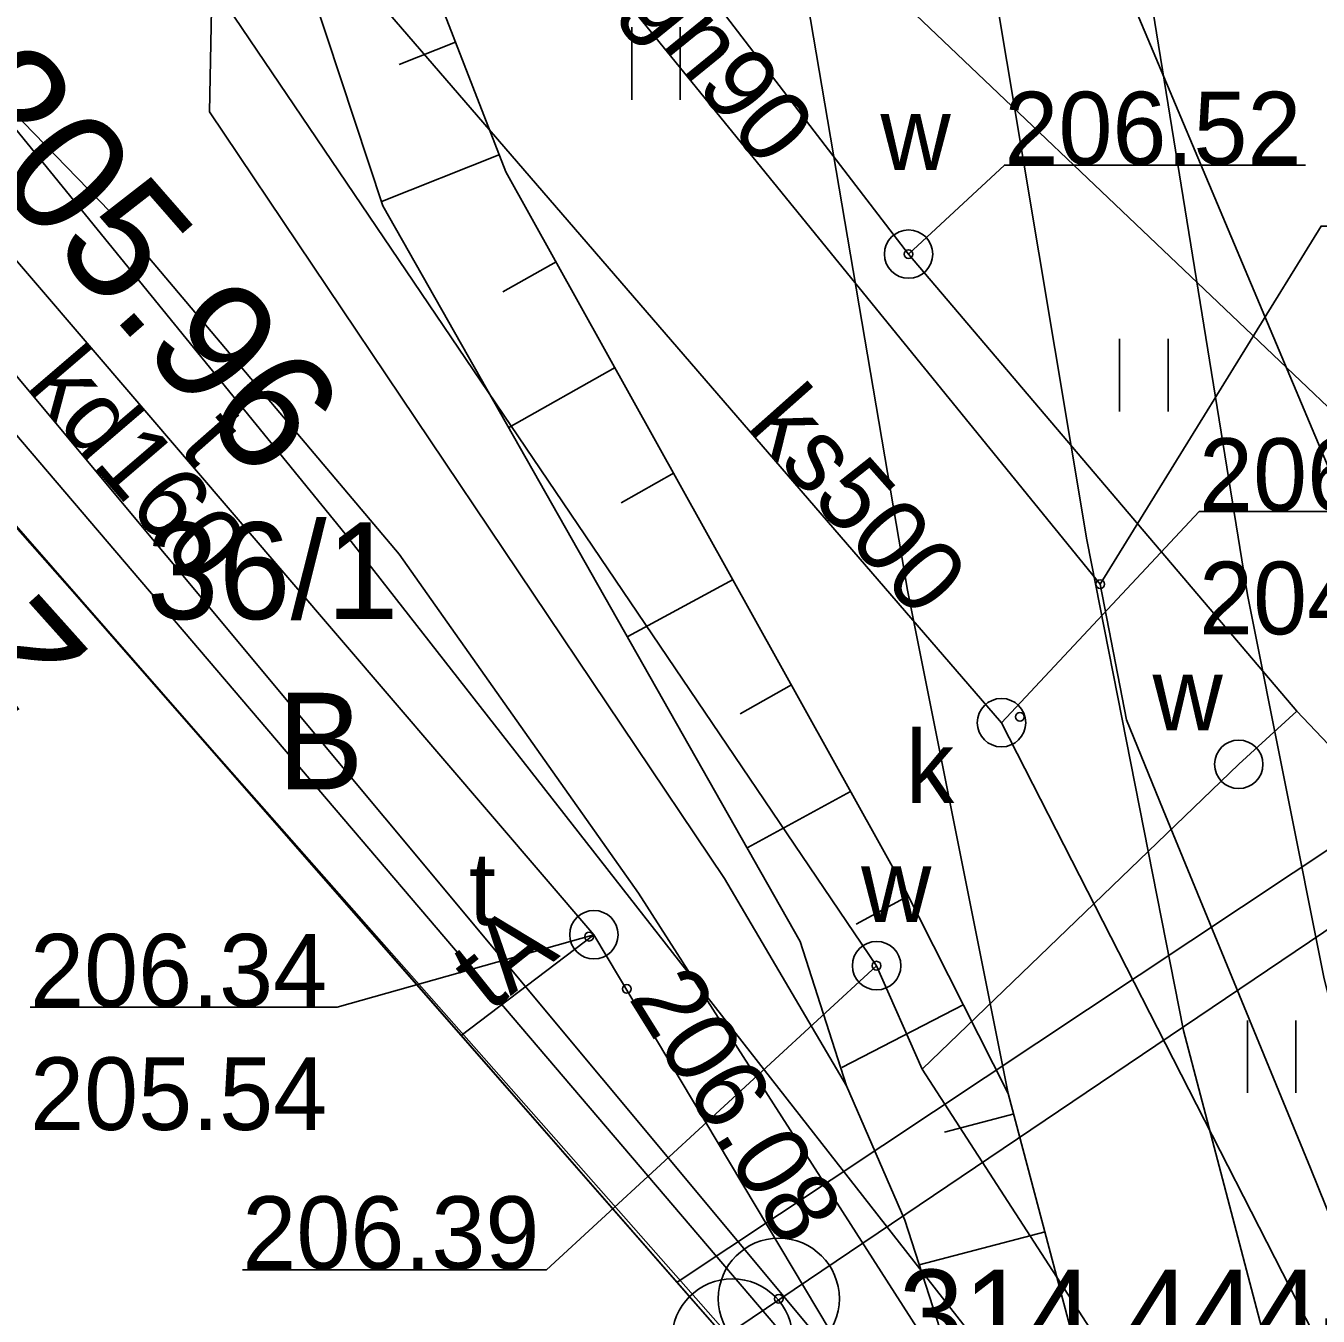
# Model space of a CAD drawing. Extents: x 6512400 to 6513200, y 6022500 to 6022750.
# Drawn here: x 6512830.73 to 6512844.08, y 6022634.38 to 6022647.71 of the extents above; entities that cross this region are included whole.
import ezdxf

# ---------------------------------------------------------------- set-up
doc = ezdxf.new("R2010")
doc.units = 0
for name, color, linetype in [('121-Punkt osnowy szczegółowej', 7, 'Continuous'), ('121-Punkt osnowy szczegółowej-Atr103', 7, 'Continuous'), ('210-oznaczenie konturu użytku gruntowego', 7, 'Continuous'), ('211-numer działki ewidencyjnej', 7, 'Continuous'), ('216-obręb ewidencyjny', 7, 'Continuous'), ('218-kontur użytku gruntowego', 7, 'Continuous'), ('219-działka ewidencyjna', 7, 'Continuous'), ('238-Punkt adresowy budynku', 7, 'Continuous'), ('312-budynek ewidencyjny', 7, 'Continuous'), ('820-Skarpa nieumocniona', 7, 'Continuous'), ('823-Szczyt skarpy nieumocninej', 7, 'Continuous'), ('824-Podnóże skarpy nieumocninej', 7, 'Continuous'), ('940-Trawnik symb. poj.', 7, 'Continuous'), ('chodnik (powierzchnia)', 7, 'Continuous'), ('krawężnik (linia)', 7, 'Continuous'), ('przewód ciepłowniczy (linia)', 7, 'Continuous'), ('przewód elektroenergetyczny (linia)', 7, 'Continuous'), ('przewód gazowy (linia)', 7, 'Continuous'), ('przewód gazowy (linia)-Atr1', 7, 'Continuous'), ('przewód kanalizacyjny (linia)', 7, 'Continuous'), ('przewód kanalizacyjny (linia)-Atr1', 7, 'Continuous'), ('przewód telekomunikacyjny (linia)', 7, 'Continuous'), ('przewód telekomunikacyjny (linia)-Atr1', 7, 'Continuous'), ('przewód wodociągowy (linia)', 7, 'Continuous'), ('punkt o określonej wysokości (sieć gazowa)', 7, 'Continuous'), ('punkt o określonej wysokości (sieć gazowa)-Atr2', 7, 'Continuous'), ('punkt o określonej wysokości (sieć kanalizacyjna)', 7, 'Continuous'), ('punkt o określonej wysokości (sieć kanalizacyjna)-Atr2', 7, 'Continuous'), ('punkt o określonej wysokości (sieć kanalizacyjna)-Atr3', 7, 'Continuous'), ('punkt o określonej wysokości (sieć telekomunikacyjna)', 7, 'Continuous'), ('punkt o określonej wysokości (sieć telekomunikacyjna)-Atr2', 7, 'Continuous'), ('punkt o określonej wysokości (sieć telekomunikacyjna)-Atr3', 7, 'Continuous'), ('punkt o określonej wysokości (sieć wodociągowa)', 7, 'Continuous'), ('punkt o określonej wysokości (sieć wodociągowa)-Atr2', 7, 'Continuous'), ('rura ochronna - przewód gazowy (linia)', 7, 'Continuous'), ('właz okrągły - siec kanalizacyjna (punkt)', 7, 'Continuous'), ('właz okrągły - siec kanalizacyjna (punkt)-Atr17', 7, 'Continuous'), ('właz okrągły - siec telekomunikacyjna (punkt)', 7, 'Continuous'), ('właz okrągły - siec telekomunikacyjna (punkt)-Atr17', 7, 'Continuous'), ('właz okrągły - siec wodociągowa (punkt)', 7, 'Continuous'), ('właz okrągły - siec wodociągowa (punkt)-Atr17', 7, 'Continuous')]:
    doc.layers.add(name, color=color, linetype=linetype)

# ---------------------------------------------------------------- blocks, each defined once
blk = doc.blocks.new('PW01')
blk.add_circle((0, 0), 0.045)
blk = doc.blocks.new('US22')
blk.add_circle((0, 0), 0.25)
blk = doc.blocks.new('940P')
for p, q in [((-0.25, -0.375), (-0.25, 0.375)), ((0.25, -0.375), (0.25, 0.375))]:
    blk.add_line(p, q)
blk = doc.blocks.new('121')
for radius in [0.625, 0.045]:
    blk.add_circle((0, 0), radius)

msp = doc.modelspace()

# ---------------------------------------------------------------- linework, layer by layer
at = {"layer": '216-obręb ewidencyjny'}
for points in [[(6512836.687, 6022675.173), (6512833.61, 6022675.02), (6512828.67, 6022670.98), (6512801.96, 6022670.34), (6512810.18, 6022663.28), (6512825.37, 6022649.66), (6512838.47, 6022634.29), (6512852.25, 6022608.25), (6512853.17, 6022604.51), (6512855.78, 6022583.95), (6512858.85, 6022571.74), (6512828.23, 6022562.62), (6512818.47, 6022559.72), (6512824.714, 6022553.406)], [(6512780.7, 6022581.02), (6512806.2, 6022572.11), (6512806.62, 6022563.51), (6512811.41, 6022558.95), (6512818.47, 6022559.72), (6512828.23, 6022562.62), (6512858.85, 6022571.74), (6512855.78, 6022583.95), (6512853.17, 6022604.51), (6512852.25, 6022608.25), (6512838.47, 6022634.29), (6512825.37, 6022649.66), (6512810.18, 6022663.28), (6512801.96, 6022670.34), (6512796.96, 6022674.74), (6512790.49, 6022674.74), (6512785.56, 6022674.74), (6512768.24, 6022674.27)]]:
    msp.add_lwpolyline(points, dxfattribs=at)
at = {"layer": '218-kontur użytku gruntowego'}
for points in [[(6512835.81, 6022651.74), (6512852.34, 6022636.01)], [(6512852.34, 6022636.01), (6512835.81, 6022651.74)], [(6512838.47, 6022634.29), (6512825.37, 6022649.66)], [(6512825.37, 6022649.66), (6512838.47, 6022634.29)], [(6512838.09, 6022634.07), (6512824.77, 6022649.17)], [(6512824.77, 6022649.17), (6512838.09, 6022634.07)]]:
    msp.add_lwpolyline(points, dxfattribs=at)
at = {"layer": '219-działka ewidencyjna'}
for points in [[(6512852.34, 6022636.01), (6512835.81, 6022651.74)], [(6512838.47, 6022634.29), (6512825.37, 6022649.66)], [(6512824.77, 6022649.17), (6512838.09, 6022634.07)]]:
    msp.add_lwpolyline(points, dxfattribs=at)
at = {"layer": '312-budynek ewidencyjny'}
msp.add_lwpolyline([(6512824.72, 6022649.31), (6512838.13, 6022633.96)], dxfattribs=at)
at = {"layer": '820-Skarpa nieumocniona'}
for p, q in [((6512835.17, 6022647.54), (6512834.59, 6022647.31)), ((6512835.63, 6022646.38), (6512834.4, 6022645.89)), ((6512836.21, 6022645.27), (6512835.66, 6022644.96)), ((6512836.82, 6022644.18), (6512835.72, 6022643.56)), ((6512837.43, 6022643.09), (6512836.88, 6022642.78)), ((6512838.04, 6022641.99), (6512836.95, 6022641.4)), ((6512838.64, 6022640.9), (6512838.11, 6022640.6)), ((6512839.25, 6022639.8), (6512838.19, 6022639.22)), ((6512839.85, 6022638.72), (6512839.31, 6022638.43)), ((6512840.42, 6022637.6), (6512839.16, 6022636.95)), ((6512840.94, 6022636.47), (6512840.22, 6022636.28)), ((6512841.26, 6022635.25), (6512839.96, 6022634.91))]:
    msp.add_line(p, q, dxfattribs=at)
at = {"layer": '823-Szczyt skarpy nieumocninej'}
msp.add_lwpolyline([(6512833.8, 6022651.69), (6512834.92, 6022648.19), (6512835.69, 6022646.2), (6512839.8, 6022638.81), (6512840.88, 6022636.68), (6512842.42, 6022630.86), (6512843.78, 6022626.35)], dxfattribs=at)
at = {"layer": '824-Podnóże skarpy nieumocninej'}
msp.add_lwpolyline([(6512843.78, 6022626.35), (6512842.81, 6022626.09), (6512839.81, 6022635.37), (6512839.21, 6022636.76), (6512838.73, 6022638.25), (6512834.42, 6022645.85), (6512833.69, 6022648.06), (6512833.8, 6022651.69)], dxfattribs=at)
at = {"layer": 'chodnik (powierzchnia)'}
msp.add_lwpolyline([(6512845.61, 6022610.5), (6512844.69, 6022613.44), (6512844.06, 6022613.28), (6512843.41, 6022615.01), (6512844.01, 6022615.23), (6512838.87, 6022629.83), (6512839.52, 6022630.32), (6512838.94, 6022631.84), (6512838.15, 6022631.88), (6512837.86, 6022632.79), (6512838.13, 6022633.96), (6512826.89, 6022646.81), (6512825.11, 6022648.85), (6512824.32, 6022649.76), (6512820.29, 6022654.03), (6512817.62, 6022656.88), (6512816.1, 6022658.5), (6512810.3, 6022663.44), (6512802.06, 6022670.47), (6512797.05, 6022674.74)], dxfattribs=at)
for points in [[(6512832.77, 6022654.07), (6512832.63, 6022646.82), (6512837.95, 6022638.9), (6512839.21, 6022636.76), (6512839.81, 6022635.37), (6512842.81, 6022626.09), (6512843.78, 6022626.35), (6512842.42, 6022630.86), (6512840.88, 6022636.68), (6512839.84, 6022641.88), (6512838.78, 6022648.12), (6512838.09, 6022653.46), (6512836.3, 6022653.4), (6512834.86, 6022653.53), (6512833.61, 6022653.83)], [(6512840.07, 6022653.59), (6512840.7, 6022648.33), (6512841.69, 6022642.4), (6512842.69, 6022637.33), (6512844.27, 6022631.32), (6512848.17, 6022618.59), (6512848.25, 6022618.32), (6512848.4, 6022617.84), (6512848.64, 6022617), (6512849.8, 6022613.04), (6512850.26, 6022613.71), (6512850.75, 6022614.71), (6512849.55, 6022618.93), (6512847.18, 6022626.74), (6512845.1, 6022633.98), (6512844.14, 6022637.88), (6512843.35, 6022641.83), (6512842.14, 6022649.32), (6512841.8, 6022651.66)]]:
    msp.add_lwpolyline(points, close=True, dxfattribs=at)
at = {"layer": 'krawężnik (linia)'}
msp.add_lwpolyline([(6512841.8, 6022651.66), (6512842.14, 6022649.32), (6512843.35, 6022641.83), (6512844.14, 6022637.88), (6512845.1, 6022633.98), (6512847.18, 6022626.74), (6512849.55, 6022618.93), (6512850.75, 6022614.71)], dxfattribs=at)
at = {"layer": 'przewód ciepłowniczy (linia)'}
for points in [[(6512837.46, 6022634.73), (6512851.24, 6022643.89)], [(6512852.19, 6022643.78), (6512837.95, 6022634.17)]]:
    msp.add_lwpolyline(points, dxfattribs=at)
at = {"layer": 'przewód elektroenergetyczny (linia)'}
for points in [[(6512763.38, 6022676.06), (6512798.79, 6022676.04), (6512803.06, 6022673.02), (6512807.84, 6022668.96), (6512815.24, 6022662.53), (6512819.98, 6022657.77), (6512831.6, 6022645.79), (6512834.59, 6022642.25), (6512837.06, 6022638.75), (6512840.02, 6022634.13), (6512842.26, 6022630.04), (6512846.03, 6022621.35), (6512846.58, 6022618.9), (6512847.6, 6022616.23), (6512852.12, 6022605.09), (6512853.39, 6022601.13), (6512855.57, 6022592.48), (6512858.1, 6022582.86), (6512868.09, 6022584.49), (6512870.03, 6022584.23), (6512871.36, 6022584.34), (6512875.65, 6022585.56), (6512879.74, 6022586.61), (6512881.754, 6022587.357)], [(6512802.27, 6022673.66), (6512807.42, 6022670.09), (6512811.38, 6022666.87), (6512814.66, 6022663.43), (6512826.4, 6022651.65), (6512827.82, 6022650.09), (6512834.03, 6022642.46), (6512842.84, 6022631.19), (6512844.67, 6022626.95), (6512847.57, 6022619.87), (6512849.81, 6022612.67), (6512853.56, 6022600.08), (6512856.46, 6022588.83), (6512861.26, 6022569.82), (6512861.768, 6022567.654)]]:
    msp.add_lwpolyline(points, dxfattribs=at)
at = {"layer": 'przewód gazowy (linia)'}
msp.add_lwpolyline([(6512847.18, 6022613.76), (6512846.63, 6022615.41), (6512849.08, 6022617.22), (6512845.94, 6022626.61), (6512846.16, 6022628.38), (6512844.18, 6022631.79), (6512844.23, 6022632.26), (6512844.43, 6022634.25), (6512844.47, 6022634.75), (6512844, 6022635.91), (6512842.48, 6022639.61), (6512842.1, 6022640.54), (6512841.83, 6022641.94), (6512833.52, 6022652.16), (6512828.68, 6022655.12), (6512826.33, 6022655.65), (6512824.93, 6022656.06), (6512819.76, 6022660.64)], dxfattribs=at)
at = {"layer": 'przewód kanalizacyjny (linia)'}
for points in [[(6512809.75, 6022675.66), (6512823.01, 6022660.61), (6512831.4, 6022651.41), (6512840.81, 6022640.51)], [(6512853.94, 6022620), (6512836.1, 6022662.34)], [(6512825.42, 6022650.35), (6512838.94, 6022634.13)], [(6512853.7, 6022614.72), (6512848.55, 6022625.36), (6512840.81, 6022640.51)]]:
    msp.add_lwpolyline(points, dxfattribs=at)
at = {"layer": 'przewód telekomunikacyjny (linia)'}
for points in [[(6512829.25, 6022646.9), (6512836.6, 6022638.32)], [(6512836.6, 6022638.32), (6512835.23, 6022637.28)], [(6512836.6, 6022638.32), (6512844.42, 6022625.21), (6512848.91, 6022613.6), (6512851.86, 6022605.02), (6512853.91, 6022597.19), (6512860.14, 6022571.94), (6512860.33, 6022571.18)]]:
    msp.add_lwpolyline(points, dxfattribs=at)
at = {"layer": 'przewód wodociągowy (linia)'}
for points in [[(6512809.35, 6022681.88), (6512813.75, 6022676.76), (6512817.99, 6022672.04), (6512824.14, 6022665.03), (6512827.96, 6022660.57), (6512832.92, 6022654.39), (6512839.85, 6022645.35)], [(6512839.52, 6022638), (6512830.11, 6022651.9), (6512829.45, 6022652.92)], [(6512843.86, 6022640.63), (6512839.85, 6022645.35)], [(6512848.7, 6022639.72), (6512846.14, 6022638.23), (6512843.86, 6022640.63), (6512843.26, 6022640.08)], [(6512843.26, 6022640.08), (6512839.99, 6022636.93)], [(6512855.66, 6022621.07), (6512846.88, 6022626.34), (6512844.27, 6022630.32), (6512839.99, 6022636.93), (6512839.52, 6022638)]]:
    msp.add_lwpolyline(points, dxfattribs=at)
at = {"layer": 'punkt o określonej wysokości (sieć gazowa)-Atr2'}
msp.add_lwpolyline([(6512841.83, 6022641.94), (6512844.11, 6022645.64), (6512847.251, 6022645.64)], dxfattribs=at)
at = {"layer": 'punkt o określonej wysokości (sieć kanalizacyjna)-Atr2'}
msp.add_lwpolyline([(6512840.81, 6022640.51), (6512842.85, 6022642.69), (6512845.991, 6022642.69)], dxfattribs=at)
at = {"layer": 'punkt o określonej wysokości (sieć telekomunikacyjna)-Atr2'}
msp.add_lwpolyline([(6512836.6, 6022638.32), (6512833.95, 6022637.57), (6512830.777, 6022637.57)], dxfattribs=at)
at = {"layer": 'punkt o określonej wysokości (sieć wodociągowa)-Atr2'}
for points in [[(6512839.85, 6022645.35), (6512840.84, 6022646.27), (6512843.949, 6022646.27)], [(6512839.52, 6022638), (6512836.11, 6022634.86), (6512832.969, 6022634.86)]]:
    msp.add_lwpolyline(points, dxfattribs=at)
at = {"layer": 'rura ochronna - przewód gazowy (linia)'}
msp.add_lwpolyline([(6512842.48, 6022639.61), (6512844, 6022635.91)], dxfattribs=at)

# ---------------------------------------------------------------- block references
at = {"layer": '121-Punkt osnowy szczegółowej'}
for p in [(6512838.51, 6022634.56), (6512838.03, 6022634.14)]:
    msp.add_blockref('121', p, dxfattribs=at)
at = {"layer": '940-Trawnik symb. poj.'}
for p in [(6512837.24, 6022647.32), (6512842.28, 6022644.1), (6512843.6, 6022637.06)]:
    msp.add_blockref('940P', p, dxfattribs=at)
at = {"layer": 'punkt o określonej wysokości (sieć gazowa)'}
msp.add_blockref('PW01', (6512841.83, 6022641.94), dxfattribs=at)
at = {"layer": 'punkt o określonej wysokości (sieć kanalizacyjna)'}
msp.add_blockref('PW01', (6512841, 6022640.57), dxfattribs=at)
at = {"layer": 'punkt o określonej wysokości (sieć telekomunikacyjna)', "rotation": 124.216}
msp.add_blockref('PW01', (6512836.55, 6022638.3), dxfattribs=at)
at = {"layer": 'punkt o określonej wysokości (sieć telekomunikacyjna)'}
msp.add_blockref('PW01', (6512836.94, 6022637.76), dxfattribs=at)
at = {"layer": 'punkt o określonej wysokości (sieć wodociągowa)', "rotation": 40.804}
msp.add_blockref('PW01', (6512839.85, 6022645.35), dxfattribs=at)
at = {"layer": 'punkt o określonej wysokości (sieć wodociągowa)'}
msp.add_blockref('PW01', (6512839.52, 6022638), dxfattribs=at)
at = {"layer": 'właz okrągły - siec kanalizacyjna (punkt)'}
msp.add_blockref('US22', (6512840.81, 6022640.51), dxfattribs=at)
at = {"layer": 'właz okrągły - siec telekomunikacyjna (punkt)', "rotation": 124.216}
msp.add_blockref('US22', (6512836.6, 6022638.32), dxfattribs=at)
at = {"layer": 'właz okrągły - siec wodociągowa (punkt)'}
for p, rotation in [((6512839.85, 6022645.35), 40.804), ((6512843.26, 6022640.08), 43.175)]:
    msp.add_blockref('US22', p, dxfattribs=dict(at, rotation=rotation))
msp.add_blockref('US22', (6512839.52, 6022638), dxfattribs=at)

# ---------------------------------------------------------------- texts
at = {"layer": '121-Punkt osnowy szczegółowej-Atr103'}
msp.add_text('314.444-112905', height=0.9, dxfattribs=at).set_placement((6512839.75, 6022633.96))
at = {"layer": '210-oznaczenie konturu użytku gruntowego'}
msp.add_text('B', height=1, dxfattribs=at).set_placement((6512833.33, 6022639.82))
at = {"layer": '211-numer działki ewidencyjnej'}
msp.add_text('36/1', height=1, dxfattribs=at).set_placement((6512831.98, 6022641.58))
at = {"layer": '238-Punkt adresowy budynku'}
msp.add_text('2', height=1.25, rotation=131.826, dxfattribs=at).set_placement((6512831.43, 6022641.21))
at = {"layer": 'przewód gazowy (linia)-Atr1'}
msp.add_text('gn90', height=0.75, rotation=309.115, dxfattribs=at).set_placement((6512836.94, 6022647.95))
at = {"layer": 'przewód kanalizacyjny (linia)-Atr1'}
for s, rotation, p in [('kd160', 310.601, (6512830.72, 6022643.98)), ('ks500', 311.599, (6512838.17, 6022643.57))]:
    msp.add_text(s, height=0.75, rotation=rotation, dxfattribs=at).set_placement(p)
at = {"layer": 'przewód telekomunikacyjny (linia)-Atr1'}
for s, rotation, p in [('t', 311.377, (6512832.3, 6022643.34)), ('tA', 38.596, (6512835.52, 6022637.51))]:
    msp.add_text(s, height=0.75, rotation=rotation, dxfattribs=at).set_placement(p)
at = {"layer": 'punkt o określonej wysokości (sieć kanalizacyjna)-Atr2'}
msp.add_text('206.43', height=0.75, dxfattribs=at).set_placement((6512842.85, 6022642.698))
at = {"layer": 'punkt o określonej wysokości (sieć kanalizacyjna)-Atr3'}
msp.add_text('204.09', height=0.75, dxfattribs=at).set_placement((6512842.85, 6022641.423))
at = {"layer": 'punkt o określonej wysokości (sieć telekomunikacyjna)'}
msp.add_text('205.96', height=1.25, rotation=311.119, dxfattribs=at).set_placement((6512829.77, 6022646.83))
at = {"layer": 'punkt o określonej wysokości (sieć telekomunikacyjna)-Atr2'}
msp.add_text('206.34', height=0.75, dxfattribs=at).set_placement((6512830.777, 6022637.578))
msp.add_text('206.08', height=0.75, rotation=301.907, dxfattribs=at).set_placement((6512836.95, 6022637.67))
at = {"layer": 'punkt o określonej wysokości (sieć telekomunikacyjna)-Atr3'}
msp.add_text('205.54', height=0.75, dxfattribs=at).set_placement((6512830.777, 6022636.303))
at = {"layer": 'punkt o określonej wysokości (sieć wodociągowa)-Atr2'}
for s, p in [('206.52', (6512840.84, 6022646.277)), ('206.39', (6512832.969, 6022634.868))]:
    msp.add_text(s, height=0.75, dxfattribs=at).set_placement(p)
at = {"layer": 'właz okrągły - siec kanalizacyjna (punkt)-Atr17'}
msp.add_text('k', height=0.75, dxfattribs=at).set_placement((6512839.82, 6022639.68))
at = {"layer": 'właz okrągły - siec telekomunikacyjna (punkt)-Atr17'}
msp.add_text('t', height=0.75, dxfattribs=at).set_placement((6512835.31, 6022638.42))
at = {"layer": 'właz okrągły - siec wodociągowa (punkt)-Atr17'}
for p in [(6512839.56, 6022646.22), (6512842.37, 6022640.43), (6512842.37, 6022640.43), (6512839.36, 6022638.45)]:
    msp.add_text('w', height=0.75, dxfattribs=at).set_placement(p)

doc.saveas('drawing.dxf')
